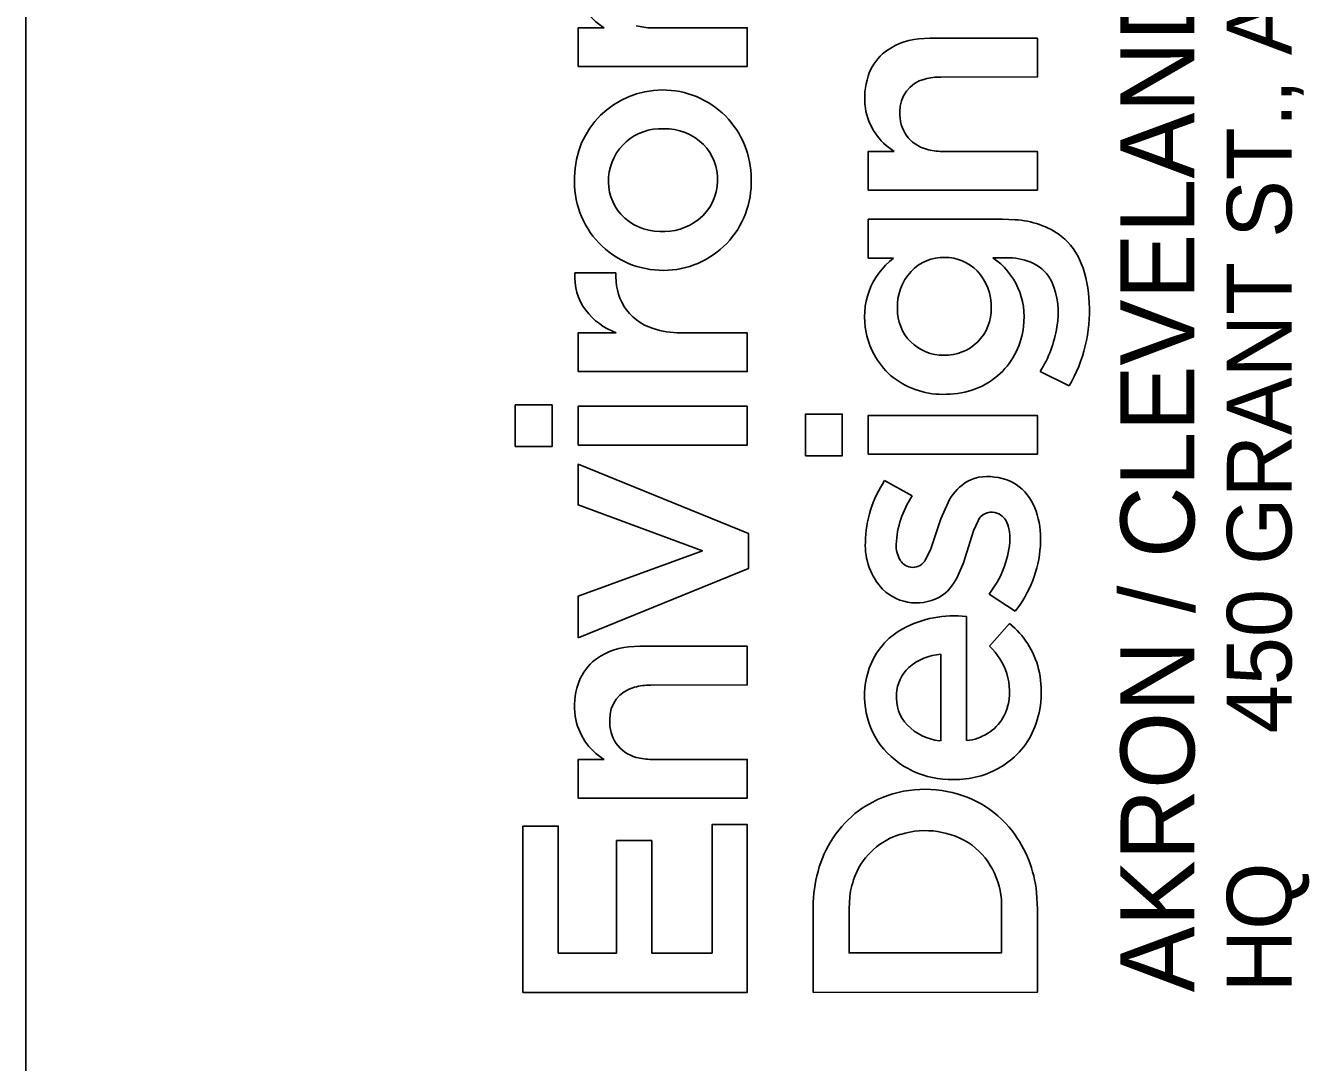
# Model space of a CAD drawing. Extents: x 0 to 34, y 0 to 22.
# Drawn here: x 32 to 32.989, y 2.584 to 3.382 of the extents above; entities that cross this region are included whole.
import ezdxf

# ---------------------------------------------------------------- set-up
doc = ezdxf.new("R2010")
doc.units = 0
doc.layers.add('SH_Border', color=7, linetype='Continuous')
doc.layers.add('SH_Data', color=7, linetype='Continuous')

msp = doc.modelspace()

# ---------------------------------------------------------------- linework, layer by layer
at = {"layer": 'SH_Border'}
msp.add_line((32, 0.5), (32, 21.5), dxfattribs=at)
at = {"layer": 'SH_Data'}
for p, q in [((32.42542, 3.38066), (32.44552, 3.38071)), ((32.42542, 3.35086), (32.42542, 3.38066)), ((32.48222, 3.38071), (32.55569, 3.38071)), ((32.55569, 3.38071), (32.55571, 3.35096)), ((32.68784, 3.3722), (32.69634, 3.37266)), ((32.69634, 3.37266), (32.77916, 3.37266)), ((32.77916, 3.37266), (32.77917, 3.34287)), ((32.55571, 3.35096), (32.42542, 3.35086)), ((32.77917, 3.34287), (32.70485, 3.3428)), ((32.64888, 3.2855), (32.66897, 3.28555)), ((32.64888, 3.25569), (32.64888, 3.2855)), ((32.70568, 3.28555), (32.77915, 3.28555)), ((32.77915, 3.28555), (32.77917, 3.25579)), ((32.77917, 3.25579), (32.64888, 3.25569)), ((32.6489, 3.20336), (32.64889, 3.23322)), ((32.64889, 3.23322), (32.75236, 3.23322)), ((32.75236, 3.23322), (32.76191, 3.23285)), ((32.66836, 3.20336), (32.6489, 3.20336)), ((32.75763, 3.20356), (32.74487, 3.20361)), ((32.42299, 3.19193), (32.45454, 3.19193)), ((32.42542, 3.14577), (32.45473, 3.14579)), ((32.42542, 3.11593), (32.42542, 3.14577)), ((32.50413, 3.14581), (32.55571, 3.14573)), ((32.55571, 3.14573), (32.55565, 3.11593)), ((32.55565, 3.11593), (32.42542, 3.11593)), ((32.8036, 3.10491), (32.7812, 3.11598)), ((32.37705, 3.05818), (32.37705, 3.09026)), ((32.37705, 3.09026), (32.40543, 3.09026)), ((32.40543, 3.09026), (32.40543, 3.05818)), ((32.42542, 3.05942), (32.42542, 3.08928)), ((32.42542, 3.08928), (32.55571, 3.08928)), ((32.55571, 3.08928), (32.55571, 3.05942)), ((32.60051, 3.05111), (32.60051, 3.08319)), ((32.60051, 3.08319), (32.62889, 3.08319)), ((32.62889, 3.08319), (32.62889, 3.05111)), ((32.64888, 3.05234), (32.64888, 3.0822)), ((32.64888, 3.0822), (32.77917, 3.0822)), ((32.77917, 3.0822), (32.77917, 3.05234)), ((32.40543, 3.05818), (32.37705, 3.05818)), ((32.55571, 3.05942), (32.42542, 3.05942)), ((32.62889, 3.05111), (32.60051, 3.05111)), ((32.77917, 3.05234), (32.64888, 3.05234)), ((32.42542, 3.01327), (32.42542, 3.0446)), ((32.42542, 3.0446), (32.5567, 2.9913)), ((32.66151, 3.03207), (32.68268, 3.02025)), ((32.70483, 3.00258), (32.71036, 3.01526)), ((32.52117, 2.97798), (32.42542, 3.01327)), ((32.69675, 2.97868), (32.70483, 3.00258)), ((32.73342, 3.00101), (32.72985, 2.9933)), ((32.5567, 2.9913), (32.5567, 2.96441)), ((32.72985, 2.9933), (32.72213, 2.96882)), ((32.42542, 2.94294), (32.52117, 2.97798)), ((32.69299, 2.97117), (32.69675, 2.97868)), ((32.72213, 2.96882), (32.71822, 2.95921)), ((32.5567, 2.96441), (32.42542, 2.91086)), ((32.42542, 2.91086), (32.42542, 2.94294)), ((32.76214, 2.93141), (32.74198, 2.94469)), ((32.72453, 2.92747), (32.72463, 2.83195)), ((32.74228, 2.90465), (32.75768, 2.922)), ((32.46439, 2.90397), (32.47289, 2.90443)), ((32.47289, 2.90443), (32.55571, 2.90443)), ((32.55571, 2.90443), (32.55571, 2.87465)), ((32.70489, 2.83182), (32.70489, 2.89834)), ((32.55571, 2.87465), (32.4814, 2.87457)), ((32.70361, 2.83165), (32.70489, 2.83182)), ((32.42542, 2.81728), (32.44552, 2.81733)), ((32.42542, 2.78747), (32.42542, 2.81728)), ((32.48222, 2.81733), (32.55569, 2.81733)), ((32.55569, 2.81733), (32.55571, 2.78756)), ((32.55571, 2.78756), (32.42542, 2.78747)), ((32.38298, 2.63791), (32.38298, 2.76598)), ((32.38298, 2.76598), (32.41012, 2.76598)), ((32.41012, 2.76598), (32.41012, 2.66827)), ((32.52857, 2.66827), (32.52857, 2.76722)), ((32.52857, 2.76722), (32.55571, 2.76722)), ((32.55571, 2.76722), (32.55571, 2.63791)), ((32.45503, 2.66827), (32.45503, 2.75488)), ((32.45503, 2.75488), (32.48218, 2.75488)), ((32.48218, 2.75488), (32.48218, 2.66827)), ((32.63465, 2.71178), (32.63407, 2.7023)), ((32.77847, 2.71497), (32.77917, 2.7021)), ((32.60643, 2.63799), (32.60644, 2.704)), ((32.63407, 2.7023), (32.63407, 2.66838)), ((32.75149, 2.66834), (32.75153, 2.70239)), ((32.77917, 2.7021), (32.77917, 2.638)), ((32.41012, 2.66827), (32.45503, 2.66827)), ((32.48218, 2.66827), (32.52857, 2.66827)), ((32.63407, 2.66838), (32.75149, 2.66834)), ((32.55571, 2.63791), (32.38298, 2.63791)), ((32.77917, 2.638), (32.60643, 2.63799))]:
    msp.add_line(p, q, dxfattribs=at)
for points in [[(32.42542, 3.35086), (32.42542, 3.38066), (32.44552, 3.38071)], [(32.48222, 3.38071), (32.55569, 3.38071), (32.55571, 3.35096), (32.42542, 3.35086)], [(32.68784, 3.3722), (32.69634, 3.37266), (32.77916, 3.37266), (32.77917, 3.34287), (32.70485, 3.3428)], [(32.64888, 3.25569), (32.64888, 3.2855), (32.66897, 3.28555)], [(32.70568, 3.28555), (32.77915, 3.28555), (32.77917, 3.25579), (32.64888, 3.25569)], [(32.66836, 3.20336), (32.6489, 3.20336), (32.64889, 3.23322), (32.75236, 3.23322), (32.76191, 3.23285)], [(32.75763, 3.20356), (32.74487, 3.20361)], [(32.42299, 3.19193), (32.45454, 3.19193)], [(32.50413, 3.14581), (32.55571, 3.14573), (32.55565, 3.11593), (32.42542, 3.11593)], [(32.42542, 3.11593), (32.42542, 3.14577), (32.45473, 3.14579)], [(32.8036, 3.10491), (32.7812, 3.11598)], [(32.66151, 3.03207), (32.68268, 3.02025)], [(32.69299, 2.97117), (32.69675, 2.97868), (32.70483, 3.00258), (32.71036, 3.01526)], [(32.73342, 3.00101), (32.72985, 2.9933), (32.72213, 2.96882), (32.71822, 2.95921)], [(32.76214, 2.93141), (32.74198, 2.94469)], [(32.72453, 2.92747), (32.72463, 2.83195)], [(32.74228, 2.90465), (32.75768, 2.922)], [(32.46439, 2.90397), (32.47289, 2.90443), (32.55571, 2.90443), (32.55571, 2.87465), (32.4814, 2.87457)], [(32.70361, 2.83165), (32.70489, 2.83182), (32.70489, 2.89834)], [(32.42542, 2.78747), (32.42542, 2.81728), (32.44552, 2.81733)], [(32.48222, 2.81733), (32.55569, 2.81733), (32.55571, 2.78756), (32.42542, 2.78747)], [(32.77847, 2.71497), (32.77917, 2.7021), (32.77917, 2.638), (32.60643, 2.63799)], [(32.63465, 2.71178), (32.63407, 2.7023), (32.63407, 2.66838), (32.75149, 2.66834), (32.75153, 2.70239)], [(32.60643, 2.63799), (32.60644, 2.704)]]:
    msp.add_lwpolyline(points, dxfattribs=at)
for points in [[(32.37705, 3.05818), (32.37705, 3.09026), (32.40543, 3.09026), (32.40543, 3.05818)], [(32.42542, 3.05942), (32.42542, 3.08928), (32.55571, 3.08928), (32.55571, 3.05942)], [(32.60051, 3.05111), (32.60051, 3.08319), (32.62889, 3.08319), (32.62889, 3.05111)], [(32.64888, 3.05234), (32.64888, 3.0822), (32.77917, 3.0822), (32.77917, 3.05234)], [(32.42542, 2.91086), (32.42542, 2.94294), (32.52117, 2.97798), (32.42542, 3.01327), (32.42542, 3.0446), (32.5567, 2.9913), (32.5567, 2.96441)], [(32.38298, 2.63791), (32.38298, 2.76598), (32.41012, 2.76598), (32.41012, 2.66827), (32.45503, 2.66827), (32.45503, 2.75488), (32.48218, 2.75488), (32.48218, 2.66827), (32.52857, 2.66827), (32.52857, 2.76722), (32.55571, 2.76722), (32.55571, 2.63791)]]:
    msp.add_lwpolyline(points, close=True, dxfattribs=at)
for centre, radius, start, end in [((32.47027, 3.42141), 0.04763, 188.96462, 238.69865), ((32.47027, 3.42141), 0.04763, 188.96462, 238.69865), ((32.48183, 3.42286), 0.04215, 254.08913, 270.52838), ((32.48183, 3.42286), 0.04215, 254.08913, 270.52838), ((32.69216, 3.32251), 0.04988, 94.97056, 130.22484), ((32.69216, 3.32251), 0.04988, 94.97056, 130.22484), ((32.68694, 3.33085), 0.04016, 132.22383, 161.68229), ((32.68694, 3.33085), 0.04016, 132.22383, 161.68229), ((32.70217, 3.32642), 0.05602, 162.27398, 187.79173), ((32.70217, 3.32642), 0.05602, 162.27398, 187.79173), ((32.70453, 3.29679), 0.04601, 89.60515, 105.33026), ((32.70453, 3.29679), 0.04601, 89.60515, 105.33026), ((32.49014, 3.26543), 0.0674, 89.84756, 179.64047), ((32.49014, 3.26543), 0.0674, 89.84756, 179.64047), ((32.49057, 3.26474), 0.0681, 359.54009, 90.21138), ((32.49057, 3.26474), 0.0681, 359.54009, 90.21138), ((32.69828, 3.31689), 0.02498, 103.68683, 182.21395), ((32.69828, 3.31689), 0.02498, 103.68683, 182.21395), ((32.69372, 3.32624), 0.04763, 188.96462, 238.69865), ((32.69372, 3.32624), 0.04763, 188.96462, 238.69865), ((32.7008, 3.31381), 0.02757, 175.58441, 255.13816), ((32.7008, 3.31381), 0.02757, 175.58441, 255.13816), ((32.48923, 3.26263), 0.0404, 87.04809, 175.57259), ((32.48923, 3.26263), 0.0404, 87.04809, 175.57259), ((32.49204, 3.25999), 0.04299, 45.84264, 90.98008), ((32.49204, 3.25999), 0.04299, 45.84264, 90.98008), ((32.49458, 3.26421), 0.03821, 357.88569, 44.15902), ((32.49458, 3.26421), 0.03821, 357.88569, 44.15902), ((32.70529, 3.32769), 0.04215, 254.08913, 270.52838), ((32.70529, 3.32769), 0.04215, 254.08913, 270.52838), ((32.49083, 3.26209), 0.06819, 176.8344, 270.40384), ((32.49083, 3.26209), 0.06819, 176.8344, 270.40384), ((32.48729, 3.2625), 0.03848, 175.15378, 221.14706), ((32.48729, 3.2625), 0.03848, 175.15378, 221.14706), ((32.49123, 3.26139), 0.06749, 270.06243, 2.37759), ((32.49123, 3.26139), 0.06749, 270.06243, 2.37759), ((32.49446, 3.26318), 0.0383, 308.28936, 359.43468), ((32.49446, 3.26318), 0.0383, 308.28936, 359.43468), ((32.48919, 3.26607), 0.04228, 223.09994, 268.80895), ((32.48919, 3.26607), 0.04228, 223.09994, 268.80895), ((32.49096, 3.2679), 0.04418, 266.56515, 308.06078), ((32.49096, 3.2679), 0.04418, 266.56515, 308.06078), ((32.75907, 3.16789), 0.06503, 53.40344, 87.49062), ((32.75907, 3.16789), 0.06503, 53.40344, 87.49062), ((32.76517, 3.18039), 0.05141, 21.60748, 50.5577), ((32.76517, 3.18039), 0.05141, 21.60748, 50.5577), ((32.70292, 3.15813), 0.05692, 127.37482, 192.22468), ((32.70292, 3.15813), 0.05692, 127.37482, 192.22468), ((32.70693, 3.16927), 0.0346, 88.47302, 136.42562), ((32.70693, 3.16927), 0.0346, 88.47302, 136.42562), ((32.70814, 3.16963), 0.03424, 44.27195, 90.47623), ((32.70814, 3.16963), 0.03424, 44.27195, 90.47623), ((32.71421, 3.15829), 0.05472, 352.1125, 55.92295), ((32.71421, 3.15829), 0.05472, 352.1125, 55.92295), ((32.75666, 3.15725), 0.04633, 65.01687, 88.8011), ((32.75666, 3.15725), 0.04633, 65.01687, 88.8011), ((32.71141, 3.16602), 0.0401, 137.46739, 182.33237), ((32.71141, 3.16602), 0.0401, 137.46739, 182.33237), ((32.70368, 3.166), 0.03996, 358.57141, 43.53765), ((32.70368, 3.166), 0.03996, 358.57141, 43.53765), ((32.7626, 3.17155), 0.03085, 26.26808, 63.80301), ((32.7626, 3.17155), 0.03085, 26.26808, 63.80301), ((32.73069, 3.16714), 0.08835, 1.15143, 21.3627), ((32.73069, 3.16714), 0.08835, 1.15143, 21.3627), ((32.46616, 3.18882), 0.04329, 175.87313, 216.34747), ((32.46616, 3.18882), 0.04329, 175.87313, 216.34747), ((32.50087, 3.18948), 0.04639, 176.9688, 209.60636), ((32.50087, 3.18948), 0.04639, 176.9688, 209.60636), ((32.73565, 3.16154), 0.05953, 349.30734, 23.43071), ((32.73565, 3.16154), 0.05953, 349.30734, 23.43071), ((32.49514, 3.18814), 0.04079, 211.94466, 253.2028), ((32.49514, 3.18814), 0.04079, 211.94466, 253.2028), ((32.70645, 3.1637), 0.03511, 178.88208, 271.08374), ((32.70645, 3.1637), 0.03511, 178.88208, 271.08374), ((32.70818, 3.16404), 0.03546, 268.27882, 1.55016), ((32.70818, 3.16404), 0.03546, 268.27882, 1.55016), ((32.70538, 3.16244), 0.11383, 329.6388, 3.25998), ((32.70538, 3.16244), 0.11383, 329.6388, 3.25998), ((32.47466, 3.19716), 0.05511, 218.09809, 248.7907), ((32.47466, 3.19716), 0.05511, 218.09809, 248.7907), ((32.50465, 3.2165), 0.07069, 252.46555, 269.57296), ((32.50465, 3.2165), 0.07069, 252.46555, 269.57296), ((32.70463, 3.15696), 0.05837, 190.75182, 231.28919), ((32.70463, 3.15696), 0.05837, 190.75182, 231.28919), ((32.70988, 3.15708), 0.05887, 313.74196, 353.8554), ((32.70988, 3.15708), 0.05887, 313.74196, 353.8554), ((32.70738, 3.16334), 0.08771, 327.31495, 351.57478), ((32.70738, 3.16334), 0.08771, 327.31495, 351.57478), ((32.70954, 3.15901), 0.06051, 269.6361, 312.70877), ((32.70954, 3.15901), 0.06051, 269.6361, 312.70877), ((32.70632, 3.16112), 0.06269, 232.46061, 272.59022), ((32.70632, 3.16112), 0.06269, 232.46061, 272.59022), ((32.7406, 3.0026), 0.03263, 80.17192, 122.51969), ((32.7406, 3.0026), 0.03263, 80.17192, 122.51969), ((32.73636, 2.98258), 0.08973, 146.53104, 178.7571), ((32.73636, 2.98258), 0.08973, 146.53104, 178.7571), ((32.74661, 2.99713), 0.04053, 125.51182, 153.41595), ((32.74661, 2.99713), 0.04053, 125.51182, 153.41595), ((32.74278, 2.99824), 0.03667, 47.79344, 84.68918), ((32.74278, 2.99824), 0.03667, 47.79344, 84.68918), ((32.73788, 2.9946), 0.04267, 14.9966, 46.20632), ((32.73788, 2.9946), 0.04267, 14.9966, 46.20632), ((32.74519, 2.9789), 0.07495, 146.51121, 176.91007), ((32.74519, 2.9789), 0.07495, 146.51121, 176.91007), ((32.74384, 2.99631), 0.01143, 76.66094, 155.7053), ((32.74384, 2.99631), 0.01143, 76.66094, 155.7053), ((32.74397, 2.99511), 0.01256, 21.5098, 78.52618), ((32.74397, 2.99511), 0.01256, 21.5098, 78.52618), ((32.71044, 2.98674), 0.07121, 355.83062, 15.39138), ((32.71044, 2.98674), 0.07121, 355.83062, 15.39138), ((32.72592, 2.98766), 0.03209, 354.57264, 22.06805), ((32.72592, 2.98766), 0.03209, 354.57264, 22.06805), ((32.69666, 2.98238), 0.05005, 177.53659, 222.79318), ((32.69666, 2.98238), 0.05005, 177.53659, 222.79318), ((32.6931, 2.98233), 0.02276, 178.47474, 211.08679), ((32.6931, 2.98233), 0.02276, 178.47474, 211.08679), ((32.68248, 2.99149), 0.0757, 321.81101, 354.79685), ((32.68248, 2.99149), 0.0757, 321.81101, 354.79685), ((32.68952, 2.9882), 0.09219, 321.9777, 355.87384), ((32.68952, 2.9882), 0.09219, 321.9777, 355.87384), ((32.68331, 2.9767), 0.01148, 212.23676, 268.37769), ((32.68331, 2.9767), 0.01148, 212.23676, 268.37769), ((32.68342, 2.97589), 0.01067, 267.71603, 333.73375), ((32.68342, 2.97589), 0.01067, 267.71603, 333.73375), ((32.68098, 2.9758), 0.04077, 308.08772, 335.98736), ((32.68098, 2.9758), 0.04077, 308.08772, 335.98736), ((32.68599, 2.97535), 0.0375, 225.98539, 302.47965), ((32.68599, 2.97535), 0.0375, 225.98539, 302.47965), ((32.7152, 2.84414), 0.08384, 83.61499, 118.28755), ((32.7152, 2.84414), 0.08384, 83.61499, 118.28755), ((32.70239, 2.86906), 0.05583, 118.83082, 160.62438), ((32.70239, 2.86906), 0.05583, 118.83082, 160.62438), ((32.71744, 2.87167), 0.06443, 13.53365, 51.36148), ((32.71744, 2.87167), 0.06443, 13.53365, 51.36148), ((32.46871, 2.85428), 0.04988, 94.96958, 130.22249), ((32.46871, 2.85428), 0.04988, 94.96958, 130.22249), ((32.70785, 2.85609), 0.04235, 94.00805, 130.88169), ((32.70785, 2.85609), 0.04235, 94.00805, 130.88169), ((32.70378, 2.86556), 0.05486, 19.03571, 45.44059), ((32.70378, 2.86556), 0.05486, 19.03571, 45.44059), ((32.46348, 2.86263), 0.04015, 132.22192, 161.68183), ((32.46348, 2.86263), 0.04015, 132.22192, 161.68183), ((32.71041, 2.86612), 0.06437, 160.52012, 215.78311), ((32.71041, 2.86612), 0.06437, 160.52012, 215.78311), ((32.70048, 2.86628), 0.02985, 132.98507, 177.179), ((32.70048, 2.86628), 0.02985, 132.98507, 177.179), ((32.70635, 2.86921), 0.07579, 339.3542, 13.37853), ((32.70635, 2.86921), 0.07579, 339.3542, 13.37853), ((32.71069, 2.8697), 0.047, 344.60586, 17.007), ((32.71069, 2.8697), 0.047, 344.60586, 17.007), ((32.47872, 2.85819), 0.05601, 162.27355, 187.79185), ((32.47872, 2.85819), 0.05601, 162.27355, 187.79185), ((32.47482, 2.84867), 0.02498, 103.68646, 182.21874), ((32.47482, 2.84867), 0.02498, 103.68646, 182.21874), ((32.48108, 2.82856), 0.04601, 89.60494, 105.3284), ((32.48108, 2.82856), 0.04601, 89.60494, 105.3284), ((32.7017, 2.86503), 0.03115, 175.00126, 223.28301), ((32.7017, 2.86503), 0.03115, 175.00126, 223.28301), ((32.7224, 2.86715), 0.03504, 288.00773, 343.55078), ((32.7224, 2.86715), 0.03504, 288.00773, 343.55078), ((32.47026, 2.85802), 0.04762, 188.96199, 238.70369), ((32.47026, 2.85802), 0.04762, 188.96199, 238.70369), ((32.47735, 2.84558), 0.02756, 175.58538, 255.14386), ((32.47735, 2.84558), 0.02756, 175.58538, 255.14386), ((32.70891, 2.87363), 0.04231, 225.06188, 262.79738), ((32.70891, 2.87363), 0.04231, 225.06188, 262.79738), ((32.71894, 2.8652), 0.0626, 300.94269, 338.73225), ((32.71894, 2.8652), 0.0626, 300.94269, 338.73225), ((32.71253, 2.87054), 0.06872, 217.74516, 271.65431), ((32.71253, 2.87054), 0.06872, 217.74516, 271.65431), ((32.72474, 2.85216), 0.02021, 269.7003, 294.8711), ((32.72474, 2.85216), 0.02021, 269.7003, 294.8711), ((32.48183, 2.85948), 0.04215, 254.09162, 270.52835), ((32.48183, 2.85948), 0.04215, 254.09162, 270.52835), ((32.71549, 2.87241), 0.07056, 269.20477, 300.33412), ((32.71549, 2.87241), 0.07056, 269.20477, 300.33412), ((32.69229, 2.70792), 0.08641, 81.19402, 125.99844), ((32.69229, 2.70792), 0.08641, 81.19402, 125.99844), ((32.69458, 2.71132), 0.08272, 37.85208, 82.40204), ((32.69458, 2.71132), 0.08272, 37.85208, 82.40204), ((32.69387, 2.70893), 0.08654, 127.23621, 165.14796), ((32.69387, 2.70893), 0.08654, 127.23621, 165.14796), ((32.68893, 2.70782), 0.05398, 106.18808, 157.38609), ((32.68893, 2.70782), 0.05398, 106.18808, 157.38609), ((32.69279, 2.69862), 0.06389, 55.67272, 107.20935), ((32.69279, 2.69862), 0.06389, 55.67272, 107.20935), ((32.68586, 2.70567), 0.09308, 5.73329, 37.30396), ((32.68586, 2.70567), 0.09308, 5.73329, 37.30396), ((32.69291, 2.70499), 0.05867, 357.46616, 52.26647), ((32.69291, 2.70499), 0.05867, 357.46616, 52.26647), ((32.71426, 2.70281), 0.10783, 164.7861, 179.37039), ((32.71426, 2.70281), 0.10783, 164.7861, 179.37039), ((32.69829, 2.70389), 0.06412, 157.35705, 172.92755), ((32.69829, 2.70389), 0.06412, 157.35705, 172.92755)]:
    msp.add_arc(centre, radius, start, end, dxfattribs=at)

# ---------------------------------------------------------------- texts
for s, height, p in [('450 GRANT ST., AKRON, OH  44311', 0.0498462, (32.97489, 2.83738)), ('AKRON / CLEVELAND / COLUMBUS', 0.056969, (32.90012, 2.638)), ('HQ ', 0.049846, (32.97489, 2.638))]:
    msp.add_text(s, height=height, rotation=90, dxfattribs=at).set_placement(p)

doc.saveas('drawing.dxf')
